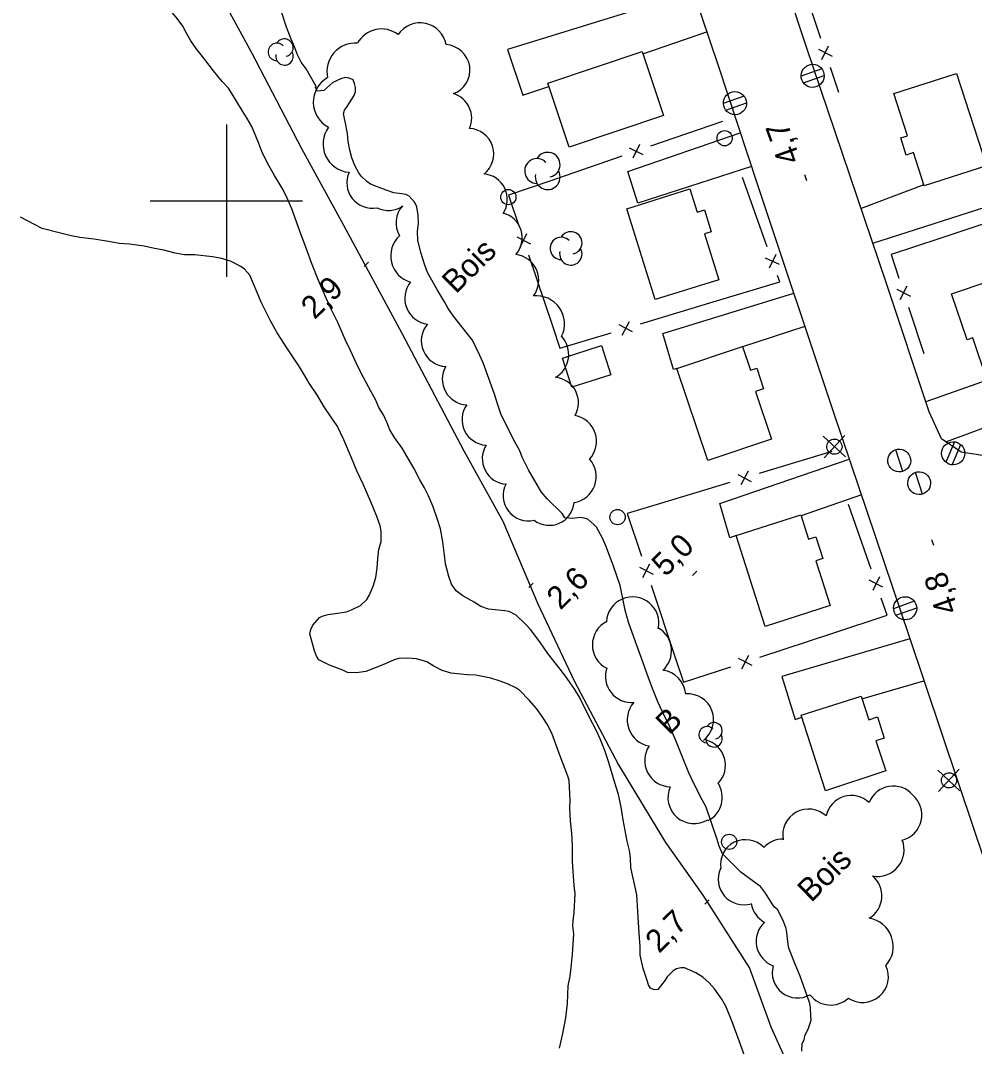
# Model space of a CAD drawing. Extents: x 381879 to 384696, y 5564785 to 5567594.
# Drawn here: x 382573 to 382698.3, y 5565288.9 to 5565423.7 of the extents above; entities that cross this region are included whole.
import ezdxf

# ---------------------------------------------------------------- set-up
doc = ezdxf.new("R2010")
doc.units = 0
for name, color, linetype in [('Niveau 19', 7, 'Continuous'), ('Niveau 2', 7, 'Continuous'), ('Niveau 21', 7, 'Continuous'), ('Niveau 22', 7, 'Continuous'), ('Niveau 3', 7, 'Continuous'), ('Niveau 31', 7, 'Continuous'), ('Niveau 36', 7, 'Continuous'), ('Niveau 37', 7, 'Continuous'), ('Niveau 4', 7, 'Continuous'), ('Niveau 44', 7, 'Continuous'), ('Niveau 61', 7, 'Continuous')]:
    doc.layers.add(name, color=color, linetype=linetype)

msp = doc.modelspace()

# ---------------------------------------------------------------- linework, layer by layer
at = {"layer": 'Niveau 19'}
for points in [[(382660.84, 5565428.99), (382657.71, 5565426.25), (382636.95, 5565419.87), (382638.97, 5565413.85), (382642.37, 5565415.02)], [(382654.74, 5565419.28), (382663.15, 5565422.17)], [(382654.08, 5565399.67), (382652.75, 5565403.85), (382667.51, 5565408.94), (382667.55, 5565408.95)], [(382669.02, 5565404.52), (382654.08, 5565399.67)], [(382684.96, 5565394.41), (382702.18, 5565399.93), (382700.34, 5565405.32), (382699.72, 5565405.09)], [(382691.67, 5565402.07), (382683.42, 5565398.97)], [(382659.22, 5565377.98), (382658.75, 5565377.82), (382657.36, 5565382.54), (382674.56, 5565387.88)], [(382676.03, 5565383.47), (382667.85, 5565380.82)], [(382694.57, 5565368.32), (382713.51, 5565375.32), (382711.5, 5565380.51), (382708.64, 5565379.5)], [(382699.96, 5565376.43), (382691.94, 5565373.59)], [(382667.01, 5565356.04), (382666.15, 5565355.71), (382664.84, 5565360.22), (382681.85, 5565366.07)], [(382683.45, 5565361.35), (382675.52, 5565358.6)], [(382689.83, 5565342.46), (382673, 5565337.52), (382674.75, 5565331.87), (382675.61, 5565332.18)], [(382683.53, 5565334.57), (382691.68, 5565336.95)]]:
    msp.add_lwpolyline(points, dxfattribs=at)
at = {"layer": 'Niveau 2'}
for points in [[(382594.28, 5565422.95), (382593.55, 5565423.94), (382592.72, 5565424.93), (382591.89, 5565425.77), (382590.2, 5565427.41), (382588.41, 5565429.08), (382587.35, 5565429.7), (382585.73, 5565430.7), (382584.9, 5565431.53), (382583.59, 5565432.7), (382582.32, 5565433.68), (382581.82, 5565433.85), (382579.68, 5565434.44), (382578.64, 5565434.41), (382575.89, 5565434.38), (382574.78, 5565434.67), (382573.72, 5565435.08), (382572.67, 5565435.8)], [(382611.79, 5565415), (382610.5, 5565417.35), (382609.85, 5565418.21), (382609.35, 5565419.18), (382608.96, 5565420.23), (382608.5, 5565421.24), (382607.9, 5565422.8), (382607.25, 5565424.8)], [(382663.43, 5565297.27), (382662.6, 5565298.02), (382661.69, 5565298.56), (382660.22, 5565299.22), (382659.71, 5565299.24), (382659.16, 5565299.12), (382658.72, 5565298.83), (382657.91, 5565298.06), (382657.67, 5565297.61), (382656.72, 5565296.37), (382656.22, 5565296.34), (382655.73, 5565296.58), (382655.47, 5565297.02), (382655.28, 5565297.55), (382654.77, 5565299.14), (382654.4, 5565300.9), (382654.36, 5565302.02), (382654.24, 5565303.77), (382654.09, 5565306.62), (382653.93, 5565308.81), (382653.74, 5565309.84), (382653.36, 5565311.39), (382653.15, 5565312.43), (382653.12, 5565313.62), (382652.96, 5565314.65), (382652.69, 5565315.87), (382652.15, 5565318.69), (382651.9, 5565320.35), (382651.52, 5565322.02), (382651.06, 5565323.52), (382650.28, 5565326.21), (382649.73, 5565327.8), (382649.14, 5565329.33), (382648.66, 5565330.35), (382647.65, 5565332.3), (382646.39, 5565334.78), (382645.79, 5565335.79), (382644.58, 5565337.55), (382643.86, 5565338.46), (382642.23, 5565340.54), (382641.29, 5565341.93), (382640, 5565343.65), (382639.32, 5565344.39), (382638.1, 5565345.58), (382637.15, 5565346.03), (382636.58, 5565346.11), (382634.43, 5565346.37), (382633.43, 5565346.71), (382632.57, 5565347.26), (382631.1, 5565348.09), (382630.22, 5565348.74), (382629.6, 5565349.62), (382629.22, 5565350.65), (382628.78, 5565352.29), (382628.68, 5565353.43), (382628.47, 5565355.2), (382628.15, 5565356.88), (382627.77, 5565358.12), (382627.16, 5565359.81), (382626.56, 5565361.25), (382626.04, 5565362.3), (382625.44, 5565363.35), (382624.62, 5565364.89), (382623.1, 5565367.48), (382622.11, 5565368.89), (382621.49, 5565369.91), (382621.11, 5565370.93), (382620.65, 5565371.87), (382620.05, 5565372.83), (382619.58, 5565373.91), (382619.03, 5565374.91), (382617.72, 5565377.34), (382617.04, 5565378.72), (382616.33, 5565380.33), (382615.63, 5565381.79), (382614.64, 5565384), (382613.84, 5565385.65), (382613.14, 5565387.21), (382612.04, 5565389.76), (382611.2, 5565391.85), (382610.63, 5565393.41), (382609.68, 5565396), (382608.62, 5565398.93), (382607.84, 5565400.74), (382607.33, 5565401.65), (382606.33, 5565403.3), (382605.47, 5565404.84), (382604.66, 5565406.45), (382604.25, 5565407.53), (382603.33, 5565409.75), (382602.73, 5565410.8), (382602.06, 5565411.84), (382600.61, 5565414.3), (382600.27, 5565414.81), (382599.47, 5565415.68), (382598.31, 5565417.07), (382597.19, 5565418.55), (382596.04, 5565419.99), (382595.35, 5565421), (382594.75, 5565422), (382594.28, 5565422.95)], [(382644.15, 5565358.92), (382642.15, 5565360.84), (382641.41, 5565361.72), (382640.84, 5565362.66), (382639.72, 5565364.65), (382638.93, 5565366.21), (382638.51, 5565367.23), (382637.96, 5565368.24), (382636.82, 5565370.47), (382636.09, 5565372.03), (382635.71, 5565373.07), (382635.22, 5565374.61), (382634.65, 5565376.19), (382633.76, 5565378.7), (382633.32, 5565379.67), (382632.35, 5565381.69), (382631.65, 5565382.57), (382629.83, 5565384.86), (382629.15, 5565385.83), (382628.67, 5565386.73), (382627.75, 5565388.25), (382626.44, 5565390.58), (382626.05, 5565391.65), (382625.56, 5565393.21), (382625.17, 5565394.81), (382625.12, 5565395.95), (382625.24, 5565397.06), (382625.2, 5565398.11), (382625.03, 5565399.22), (382624.79, 5565399.76), (382624.04, 5565400.59), (382623.57, 5565400.83), (382623.05, 5565400.93), (382621.99, 5565401.03), (382620.99, 5565401.37), (382618.94, 5565402.18), (382618.48, 5565402.53), (382617.72, 5565403.24), (382617.43, 5565403.66), (382616.87, 5565404.63), (382616.5, 5565405.63), (382616.23, 5565406.66), (382616.01, 5565407.78), (382615.93, 5565408.82), (382615.62, 5565410.4), (382615.4, 5565411.4), (382615.55, 5565411.9), (382615.9, 5565412.4), (382616.81, 5565413.82), (382616.98, 5565414.36), (382616.98, 5565414.88), (382616.86, 5565415.42), (382616.66, 5565415.88), (382616.16, 5565416.11), (382615.61, 5565416.19), (382615.04, 5565416.03), (382614, 5565415.52), (382613.62, 5565415.18), (382612.81, 5565414.5), (382611.92, 5565414.41), (382611.72, 5565414.9), (382611.79, 5565415)], [(382673.66, 5565303.87), (382673.56, 5565304.38), (382673.17, 5565305.44), (382672.45, 5565306.88), (382672.05, 5565307.21), (382671.71, 5565307.65), (382670.83, 5565309.05), (382670.19, 5565309.92), (382669.74, 5565310.24), (382667.59, 5565311.82), (382666.76, 5565312.63), (382665.21, 5565314.21), (382664.78, 5565315.21), (382664.47, 5565316.21), (382663.77, 5565318.29), (382663.04, 5565320.32), (382662.51, 5565321.3), (382661.48, 5565323.34), (382660.78, 5565324.85), (382660.11, 5565326.48), (382659.08, 5565329.09), (382658.2, 5565331.11), (382657.64, 5565332.21), (382656.7, 5565334.16), (382656.08, 5565335.69), (382655.49, 5565337.32), (382654.57, 5565339.93), (382653.78, 5565342.05), (382652.85, 5565344.63), (382652.39, 5565346.2), (382652.18, 5565347.33), (382651.74, 5565349.45), (382651.37, 5565350.6), (382650.82, 5565352.12), (382649.89, 5565354.67), (382649.42, 5565355.66), (382648.66, 5565357.11), (382648.29, 5565357.47), (382647.5, 5565358.15), (382647.01, 5565358.32), (382646.49, 5565358.4), (382645.43, 5565358.27), (382644.47, 5565358.35), (382644.21, 5565358.78), (382644.15, 5565358.92)], [(382675.64, 5565288.3), (382675.65, 5565289.3), (382675.92, 5565289.78), (382676.04, 5565290.31), (382676.5, 5565291.29), (382676.85, 5565292.37), (382676.8, 5565292.92), (382676.75, 5565294), (382676.66, 5565294.56), (382676.32, 5565295.55), (382675.4, 5565298.14), (382674.73, 5565299.71), (382673.91, 5565301.8), (382673.84, 5565302.3), (382673.66, 5565303.87)], [(382668.36, 5565286.99), (382667.39, 5565289.64), (382666.46, 5565292.16), (382665.62, 5565294.2), (382665.11, 5565295.1), (382664.14, 5565296.49), (382663.43, 5565297.27)]]:
    msp.add_lwpolyline(points, dxfattribs=at)
at = {"layer": 'Niveau 21'}
for points in [[(382720.53, 5565570.18), (382697.53, 5565546.63), (382665.88, 5565514.31), (382657.25, 5565505.32), (382653.65, 5565500.2), (382651.24, 5565495.77), (382649.27, 5565491.24), (382647.14, 5565482.76), (382646.85, 5565476.08), (382647.36, 5565470.86), (382648.52, 5565465.33), (382652.45, 5565453.49), (382656.95, 5565440.49), (382664.59, 5565417.9), (382669.82, 5565402.09), (382679.79, 5565372.18), (382689.73, 5565342.77), (382698.21, 5565317.46), (382704.14, 5565299.95), (382707.89, 5565289.64), (382710.87, 5565282.99)], [(382734.21, 5565391.84), (382717.54, 5565374.77), (382712.17, 5565371.05), (382707.53, 5565369.06), (382699.65, 5565366.49), (382696.58, 5565366.97), (382693.99, 5565368.71), (382692.37, 5565372.29), (382686.7, 5565389.28), (382676.19, 5565420.31), (382666.83, 5565448.64), (382660.42, 5565467.72), (382659.08, 5565473.74), (382659.16, 5565480.09), (382661.82, 5565489.21), (382666.49, 5565497.49), (382676.36, 5565507.68), (382696.82, 5565528.64), (382716.35, 5565548.84)]]:
    msp.add_lwpolyline(points, dxfattribs=at)
at = {"layer": 'Niveau 22'}
msp.add_lwpolyline([(382597.02, 5565431.06), (382603.35, 5565419.39), (382609.87, 5565406.87), (382615.38, 5565396.8), (382623.07, 5565382.6), (382631.2, 5565367.17), (382636.35, 5565357.89), (382640.93, 5565347.06), (382645.72, 5565336.94), (382651.55, 5565325.91), (382657.7, 5565315.69), (382662.62, 5565308.8), (382668.77, 5565299.19), (382671.57, 5565291.49), (382676.09, 5565281.36)], dxfattribs=at)
at = {"layer": 'Niveau 3'}
for p, q in [((382676.27, 5565402.63), (382676.03, 5565403.4)), ((382618.12, 5565391.36), (382618.69, 5565391.93)), ((382692.96, 5565354.7), (382692.72, 5565355.47)), ((382661.28, 5565350.79), (382661.85, 5565351.36)), ((382639.73, 5565349.21), (382640.3, 5565349.78)), ((382662.86, 5565307.6), (382663.43, 5565308.17))]:
    msp.add_line(p, q, dxfattribs=at)
at = {"layer": 'Niveau 31'}
for points in [[(382657.44, 5565411.2), (382645.04, 5565407.05), (382642.23, 5565415.45), (382654.63, 5565419.6)], [(382695.97, 5565416.73), (382699.88, 5565404.58), (382691.71, 5565401.95), (382690.3, 5565406.32), (382689.35, 5565406.01), (382688.62, 5565408.26), (382689.5, 5565408.54), (382687.73, 5565414.1)], [(382656.37, 5565387.01), (382652.62, 5565398.96), (382660.93, 5565401.57), (382661.89, 5565398.5), (382662.83, 5565398.79), (382663.71, 5565395.93), (382662.84, 5565395.66), (382664.72, 5565389.6)], [(382704.78, 5565390.97), (382708.7, 5565379.33), (382699.98, 5565376.38), (382698.09, 5565381.99), (382697.34, 5565381.73), (382695.3, 5565387.77)], [(382650.53, 5565377.13), (382645.39, 5565375.49), (382644.16, 5565379.33), (382649.3, 5565380.97)], [(382663.26, 5565365.89), (382659.22, 5565377.98), (382667.84, 5565380.85), (382668.88, 5565377.75), (382669.7, 5565378.02), (382670.61, 5565375.31), (382669.55, 5565374.95), (382671.64, 5565368.68)], [(382670.82, 5565344.06), (382667.01, 5565356.04), (382675.48, 5565358.73), (382676.49, 5565355.56), (382677.45, 5565355.87), (382678.37, 5565353.01), (382677.45, 5565352.71), (382679.36, 5565346.84)], [(382678.74, 5565322.48), (382675.54, 5565332.41), (382683.41, 5565334.94), (382684.41, 5565331.83), (382685.55, 5565332.2), (382686.46, 5565329.41), (382685.34, 5565329.04), (382686.65, 5565325.1)]]:
    msp.add_lwpolyline(points, close=True, dxfattribs=at)
at = {"layer": 'Niveau 36'}
for p, q in [((382678.26, 5565417.32), (382675.52, 5565416.36)), ((382675.84, 5565415.5), (382678.58, 5565416.46)), ((382668.03, 5565413.74), (382665.3, 5565412.76)), ((382665.63, 5565411.9), (382668.36, 5565412.88)), ((382678.44, 5565369.06), (382681.35, 5565366.34)), ((382678.54, 5565366.25), (382681.26, 5565369.16)), ((382695.67, 5565368.33), (382694.53, 5565365.66)), ((382688.9, 5565364.44), (382687.96, 5565367.28)), ((382695.39, 5565365.31), (382696.53, 5565367.98)), ((382691.5, 5565361.46), (382690.58, 5565364.32)), ((382690.39, 5565347.39), (382687.66, 5565346.41)), ((382687.99, 5565345.55), (382690.72, 5565346.53)), ((382693.5, 5565325.22), (382696.41, 5565322.5)), ((382693.6, 5565322.41), (382696.32, 5565325.32))]:
    msp.add_line(p, q, dxfattribs=at)
for centre in [(382665.48, 5565408.21), (382637.06, 5565400.48), (382651.41, 5565358.44), (382666.08, 5565315.78)]:
    msp.add_circle(centre, 1, dxfattribs=at)
for centre, major_axis, ratio in [((382677.04, 5565416.41), (-0.05, -1.52), 0.999982), ((382666.84, 5565412.82), (-0.03, 1.52), 0.999983), ((382679.91, 5565367.7), (-0.048, -0.999), 0.999982), ((382695.52, 5565366.82), (0.01, -1.52), 0.999982), ((382688.43, 5565365.87), (0.06, 1.5), 0.999982), ((382691.04, 5565362.9), (0.06, 1.5), 0.999982), ((382689.2, 5565346.47), (0.04, 1.52), 0.999982), ((382694.97, 5565323.86), (-0.048, -0.999), 0.999982)]:
    msp.add_ellipse(centre, major_axis=major_axis, ratio=ratio, dxfattribs=at)
at = {"layer": 'Niveau 37'}
for p, q in [((382677.81, 5565419.91), (382679.6, 5565419.01)), ((382678.26, 5565418.57), (382679.15, 5565420.36)), ((382654.28, 5565407.41), (382653.41, 5565405.61)), ((382652.95, 5565406.95), (382654.75, 5565406.07)), ((382638.17, 5565395.24), (382639.96, 5565394.35)), ((382638.62, 5565393.9), (382639.51, 5565395.69)), ((382672.67, 5565391.62), (382670.86, 5565392.47)), ((382672.19, 5565392.95), (382671.34, 5565391.14)), ((382688.11, 5565388.37), (382689.9, 5565387.47)), ((382688.56, 5565387.03), (382689.46, 5565388.82)), ((382653.38, 5565382.76), (382651.62, 5565383.71)), ((382652.02, 5565382.35), (382652.97, 5565384.12)), ((382667.21, 5565364.05), (382668.98, 5565363.1)), ((382668.57, 5565364.46), (382667.63, 5565362.69)), ((382654.74, 5565350.51), (382655.64, 5565352.3)), ((382654.29, 5565351.85), (382656.08, 5565350.96)), ((382685.82, 5565350.6), (382684.95, 5565348.8)), ((382686.28, 5565349.26), (382684.48, 5565350.14)), ((382669.08, 5565338.96), (382667.3, 5565339.87)), ((382667.74, 5565338.52), (382668.64, 5565340.31))]:
    msp.add_line(p, q, dxfattribs=at)
for points in [[(382674.92, 5565430.85), (382678.07, 5565421.36)], [(382679.34, 5565417.56), (382680.43, 5565414.27)], [(382665.19, 5565410.42), (382655.74, 5565407.16)], [(382651.96, 5565405.85), (382642.5, 5565402.59)], [(382642.5, 5565402.59), (382637.07, 5565400.72), (382638.43, 5565396.69)], [(382671.09, 5565393.93), (382667.81, 5565403.06)], [(382703.23, 5565398.18), (382693.74, 5565395.04)], [(382693.74, 5565395.04), (382687.35, 5565392.93), (382688.38, 5565389.82)], [(382639.7, 5565392.9), (382642.9, 5565383.42)], [(382663.98, 5565386.71), (382672.73, 5565389.35), (382672.44, 5565390.16)], [(382654.41, 5565383.81), (382663.98, 5565386.71)], [(382689.64, 5565386.03), (382691.66, 5565379.93)], [(382642.9, 5565383.42), (382643.84, 5565380.62), (382650.58, 5565382.66)], [(382679.58, 5565367.06), (382670.01, 5565364.16)], [(382666.18, 5565362.99), (382656.61, 5565360.09)], [(382656.61, 5565360.09), (382652.69, 5565358.9), (382654.56, 5565353.3)], [(382684.73, 5565351.59), (382681.77, 5565360.11)], [(382655.82, 5565349.51), (382658.99, 5565340.02)], [(382679.59, 5565343.17), (382686.82, 5565345.56), (382686.04, 5565347.81)], [(382670.09, 5565340.04), (382679.59, 5565343.17)], [(382658.99, 5565340.02), (382660.08, 5565336.74), (382666.29, 5565338.79)]]:
    msp.add_lwpolyline(points, dxfattribs=at)
at = {"layer": 'Niveau 4'}
for points in [[(382628.35, 5565338.31), (382627.27, 5565338.86), (382626.33, 5565339.45), (382624.99, 5565339.83), (382623.85, 5565339.92), (382622.62, 5565339.87), (382622.07, 5565339.69), (382620.79, 5565339.14), (382618.35, 5565338.17), (382617.1, 5565337.97), (382615.92, 5565338.05), (382615.31, 5565338.33), (382613.54, 5565338.99), (382612.14, 5565339.7), (382611.84, 5565340.19), (382611.59, 5565340.87), (382610.97, 5565343.09), (382611.1, 5565343.69), (382611.38, 5565344.25), (382612.24, 5565345.27), (382612.71, 5565345.49), (382613.38, 5565345.67), (382614.59, 5565345.81), (382615.78, 5565346.01), (382616.44, 5565346.26), (382617.64, 5565346.85), (382618.46, 5565347.63), (382618.77, 5565348.14), (382619.3, 5565349.38), (382619.63, 5565350.49), (382619.82, 5565351.74), (382619.91, 5565353.02), (382620.06, 5565354.17), (382620.34, 5565355.23), (382620.36, 5565356.6), (382620.22, 5565357.29), (382619.78, 5565358.53), (382619.01, 5565360.43), (382617.98, 5565362.76), (382617.16, 5565364.51), (382616.44, 5565366.21), (382615.46, 5565368.58), (382614.55, 5565370.45), (382613.85, 5565371.44), (382612.78, 5565373.04), (382611.96, 5565374.43), (382610.89, 5565376.04), (382610.28, 5565377.11), (382609.6, 5565378.17), (382607.93, 5565380.66), (382606.67, 5565382.65), (382605.82, 5565384.22), (382604.57, 5565386.66), (382604.05, 5565387.95), (382603.08, 5565390.21), (382602.39, 5565391.02), (382601.91, 5565391.36), (382600.62, 5565392), (382599.43, 5565392.42), (382598.17, 5565392.63), (382595.86, 5565392.88), (382594.51, 5565392.91), (382593.26, 5565393.13), (382591.77, 5565393.52), (382590.55, 5565393.72), (382589.19, 5565394.02), (382587.27, 5565394.31), (382585.92, 5565394.38), (382584.78, 5565394.6), (382582.62, 5565394.95), (382580.77, 5565395.17), (382579.63, 5565395.39), (382578.02, 5565395.78), (382575.79, 5565396.37), (382574.8, 5565396.87), (382572.94, 5565397.86)], [(382643.79, 5565288.66), (382644.21, 5565290.61), (382644.6, 5565292.67), (382644.82, 5565294.56), (382644.86, 5565295.72), (382644.93, 5565296.86), (382645.19, 5565298.15), (382645.33, 5565299.27), (382645.48, 5565301.02), (382645.68, 5565303.67), (382645.53, 5565304.81), (382645.59, 5565305.42), (382645.71, 5565306.52), (382645.86, 5565308.96), (382645.73, 5565310.06), (382645.56, 5565311.88), (382645.51, 5565313.24), (382645.49, 5565315.23), (382645.42, 5565316.94), (382645.24, 5565318.54), (382645.14, 5565320.2), (382645.18, 5565321.27), (382645.07, 5565323.86), (382644.87, 5565324.4), (382643.84, 5565327.17), (382642.78, 5565330.07), (382642.15, 5565331.25), (382641.52, 5565332.23), (382640.74, 5565333.29), (382639.81, 5565334.4), (382638.59, 5565335.65), (382638.05, 5565336), (382636.94, 5565336.54), (382635.86, 5565336.94), (382634.76, 5565337.27), (382632.8, 5565337.67), (382631.63, 5565337.74), (382629.56, 5565337.93), (382628.35, 5565338.31)]]:
    msp.add_lwpolyline(points, dxfattribs=at)
at = {"layer": 'Niveau 44'}
for centre, radius, start, end in [((382606.65, 5565419.55), 1.15, 44.1153, 269.8039), ((382607.64, 5565420.12), 1.15, 282.2692, 149.7262), ((382607.64, 5565418.97), 1.15, 166.9368, 29.6212), ((382642.23, 5565404.73), 1.63, 282.2692, 149.7262), ((382640.83, 5565403.91), 1.63, 44.1153, 269.8039), ((382642.23, 5565403.09), 1.63, 166.9368, 29.6212), ((382621.31, 5565402.09), 3.36, 243.3004, 303.5875), ((382644.01, 5565393.74), 1.47, 44.1153, 269.8039), ((382645.27, 5565394.47), 1.47, 282.2692, 149.7262), ((382645.27, 5565393.01), 1.47, 166.9368, 29.6212), ((382626.85, 5565387.17), 3.4, 140.9954, 263.0728), ((382642.92, 5565373.46), 3.36, 330.2109, 84.3296), ((382663.17, 5565329.85), 1.08, 44.1153, 269.8039), ((382664.09, 5565330.38), 1.08, 282.2692, 149.7262), ((382664.09, 5565329.31), 1.08, 166.9368, 29.6212), ((382685.56, 5565314.75), 3.51, 259.3734, 21.2067), ((382683.87, 5565302.04), 3.77, 318.1667, 80.6508)]:
    msp.add_arc(centre, radius, start, end, dxfattribs=at)
for centre, major_axis, ratio, start_param, end_param in [((382625.4, 5565419.69), (0.93, 3.57), 0.959513, 5.181062, 7.475908), ((382620.43, 5565418.88), (-1.89, 3.17), 0.993643, 5.118994, 6.807688), ((382616.92, 5565417.01), (-2.77, -2.46), 0.998671, 3.904032, 5.787103), ((382628.68, 5565417.2), (-2.89, 1.7), 0.985875, 2.450472, 5.178645), ((382615.11, 5565412.96), (0.07, -3.69), 0.998686, 3.632144, 5.792634), ((382628.9, 5565410.86), (-1.77, 2.85), 0.994219, 3.740189, 5.439221), ((382616.44, 5565407.45), (-3.4, -1.53), 0.999981, 5.222733, 7.34495), ((382631.8, 5565406.15), (-1.15, 3.15), 0.994223, 3.458887, 5.884731), ((382619.19, 5565402.36), (3.18, -1.09), 0.991438, 3.047824, 5.224191), ((382633.58, 5565400.19), (-1.92, 2.75), 0.994188, 3.521425, 5.590662), ((382625.64, 5565397.11), (-0.88, -3.24), 0.99765, 4.250383, 5.514812), ((382635.56, 5565395.1), (1.73, 2.88), 0.985, 4.537287, 6.58435), ((382625.18, 5565392.75), (-3.48, -0.84), 0.99998, 5.218583, 7.343231), ((382637.69, 5565389.57), (3.17, 1.16), 0.998431, 5.271823, 7.39704), ((382640.74, 5565383.82), (3.03, 2.12), 0.999923, 5.21849, 7.347068), ((382628.97, 5565381.59), (1.19, -3.15), 0.994209, 3.635134, 5.881437), ((382641.45, 5565379.83), (3.38, -1.07), 0.994268, 5.551259, 7.32987), ((382631.73, 5565376.54), (2.15, -2.58), 0.993714, 3.490895, 5.547055), ((382634.35, 5565371.25), (-3.26, -0.87), 0.999879, 5.405705, 7.529403), ((382645.18, 5565368.39), (3.29, 1.09), 0.998421, 5.219225, 7.341609), ((382636.98, 5565366.11), (1.06, -3.19), 0.993707, 3.835082, 5.891019), ((382645.1, 5565363.78), (3.3, -1.19), 0.990266, 5.230538, 7.345073), ((382639.69, 5565361.29), (-0.21, -3.34), 0.987392, 4.29936, 6.57825), ((382642.42, 5565360.7), (1.06, -3.17), 0.988017, 5.317218, 7.429333), ((382653.39, 5565344.53), (-3.39, 0.6), 0.998756, 3.092636, 6.401629), ((382651.53, 5565341.66), (-0.74, -3.36), 0.997417, 3.826654, 6.034231), ((382655.08, 5565340.88), (-0.64, 3.38), 0.99557, 3.687185, 5.570037), ((382653.25, 5565337.52), (1.88, -2.88), 0.996085, 3.81933, 5.789587), ((382656.96, 5565334.92), (-1.32, 3.17), 0.995539, 4.398076, 5.766284), ((382660.62, 5565331.8), (2.25, 2.59), 0.990015, 4.516978, 7.074916), ((382656.14, 5565331.79), (-3.27, -1.14), 0.999995, 5.22182, 7.348203), ((382662.17, 5565325.86), (-2.56, 2.29), 0.993816, 3.104933, 5.188787), ((382658.44, 5565326.47), (-3.08, -1.59), 0.998601, 5.221536, 7.342262), ((382661.46, 5565321.6), (2.97, -1.73), 0.994951, 3.246957, 5.795765), ((382661.76, 5565321.67), (1.61, -3.05), 0.986989, 6.266007, 7.930633), ((382687.63, 5565319.71), (-2.43, -2.38), 0.999759, 3.072785, 5.133145), ((382682.15, 5565318.48), (-0.91, 3.27), 0.997112, 5.254533, 7.37557), ((382688.01, 5565319.31), (0.84, 3.29), 0.999937, 3.636165, 5.828976), ((382676.52, 5565316.69), (-3.22, -1.09), 0.999937, 3.637511, 6.143456), ((382668.29, 5565312.72), (-2.61, 2.17), 0.977515, 4.614604, 7.123314), ((382673.14, 5565312.74), (-2.76, -1.98), 0.999984, 4.077576, 4.914539), ((382668.03, 5565310.9), (2.78, -1.94), 0.999437, 3.331449, 5.61296), ((382682.75, 5565308.68), (0.65, 3.34), 0.999748, 3.86988, 5.787904), ((382672.34, 5565308.19), (-0.61, -3.34), 0.999064, 5.048182, 5.970923), ((382673.02, 5565302.7), (0.5, -3.36), 0.999605, 3.73435, 5.786811), ((382675.1, 5565298.66), (-1.7, -2.94), 0.986314, 4.979271, 7.311969), ((382683.62, 5565298.07), (2.02, 2.72), 0.999984, 3.188659, 5.792114), ((382679.41, 5565297.73), (2.2, -2.58), 0.999418, 4.649763, 6.334461)]:
    msp.add_ellipse(centre, major_axis=major_axis, ratio=ratio, start_param=start_param, end_param=end_param, dxfattribs=at)
at = {"layer": 'Niveau 61'}
for points in [[(382600, 5565410), (382600, 5565400), (382600, 5565390)], [(382590, 5565400), (382600, 5565400), (382610, 5565400)]]:
    msp.add_lwpolyline(points, dxfattribs=at)

# ---------------------------------------------------------------- texts
at = {"layer": 'Niveau 3'}
for s, rotation, p in [('4,7  ', 109.5592, (382675.48, 5565405.4)), ('2,9', 44.7717, (382611.61, 5565384.3)), ('5,0', 44.7717, (382657.72, 5565350.49)), ('2,6', 44.7717, (382643.9, 5565346.14)), ('4,8  ', 108.9943, (382696.24, 5565346.24)), ('2,7', 44.7717, (382656.87, 5565301.05))]:
    msp.add_text(s, height=3, rotation=rotation, dxfattribs=at).set_placement(p)
at = {"layer": 'Niveau 44'}
for s, p in [('Bois', (382630.16, 5565387.68)), ('B', (382658.22, 5565329.7)), ('Bois', (382676.86, 5565307.73))]:
    msp.add_text(s, height=3, rotation=44.7707, dxfattribs=at).set_placement(p)

doc.saveas('drawing.dxf')
